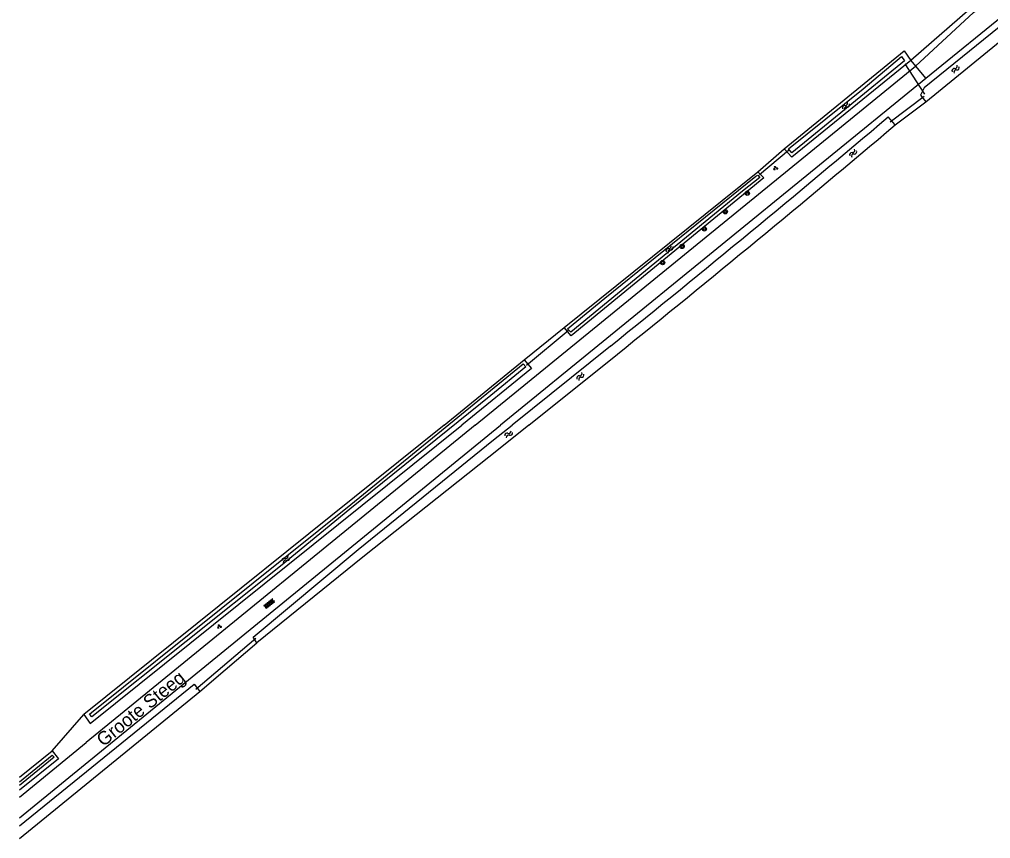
# Model space of a CAD drawing. Extents: x 136000 to 141014, y 402000 to 403500.
# Drawn here: x 136000 to 136180.8, y 402923.1 to 403075.5 of the extents above; entities that cross this region are included whole.
import ezdxf

# ---------------------------------------------------------------- set-up
doc = ezdxf.new("R2010")
doc.units = 0
for name, color, linetype in [('gg-anno-openbare ruimte label', 7, 'Continuous'), ('gg-knt-bronhoudergrens', 7, 'Continuous'), ('gg-knt-onverhard', 7, 'Continuous'), ('gg-kntw-bovenkant insteek waterloop', 7, 'Continuous'), ('gg-kntw-waterlijn', 7, 'Continuous'), ('gg-kwrk-duiker nz buis', 7, 'Continuous'), ('gt-grn-groengrens', 7, 'Continuous'), ('gt-grn-weggrens', 7, 'Continuous'), ('gt-symb-boom', 7, 'Continuous'), ('gt-symb-groenvak', 7, 'Continuous'), ('gt-symb-overige verharding', 7, 'Continuous'), ('gt-symb-watersymbool', 7, 'Continuous')]:
    doc.layers.add(name, color=color, linetype=linetype)

# ---------------------------------------------------------------- blocks, each defined once
blk = doc.blocks.new('gt0-BOOM')
at = {"layer": 'gt-symb-boom'}
for radius in [0.4, 0.2]:
    blk.add_circle((0, 0), radius, dxfattribs=at)
blk = doc.blocks.new('gt0-GRVAK')
at = {"layer": 'gt-symb-groenvak'}
for p, q in [((-0.11, 0.19), (-0.23, 0.24)), ((-0.18, 0.15), (0.09, 0.15)), ((-0.09, 0.21), (-0.16, 0.32)), ((-0.05, 0.21), (-0.05, 0.39)), ((0, 0.21), (0.06, 0.32)), ((0.02, 0.19), (0.13, 0.24)), ((0.26, -0.05), (0.2, 0.06)), ((0.31, -0.05), (0.31, 0.13)), ((0.35, -0.05), (0.41, 0.06)), ((-0.24, -0.23), (-0.36, -0.18)), ((-0.32, -0.26), (-0.05, -0.26)), ((-0.23, -0.21), (-0.29, -0.1)), ((-0.18, -0.2), (-0.18, -0.02)), ((-0.14, -0.21), (-0.07, -0.1)), ((-0.12, -0.23), (0, -0.18)), ((0.24, -0.07), (0.12, -0.02)), ((0.17, -0.11), (0.44, -0.11)), ((0.37, -0.07), (0.49, -0.02))]:
    blk.add_line(p, q, dxfattribs=at)
blk = doc.blocks.new('gt0-WA')
at = {"layer": 'gt-symb-watersymbool'}
for centre, start, end in [((-0.32, 0.02), 28.0725, 151.9275), ((0.43, 0.42), 208.0725, 331.9275), ((-0.32, -0.43), 28.0725, 151.9275), ((0.43, -0.03), 208.0725, 331.9275)]:
    blk.add_arc(centre, 0.425, start, end, dxfattribs=at)
blk = doc.blocks.new('gt0-OVH')
at = {"layer": 'gt-symb-overige verharding'}
for points in [[(-0.97, 0.3), (-0.97, 0.31), (-0.96, 0.32), (-0.97, 0.33), (-0.97, 0.34), (-0.98, 0.35), (-0.99, 0.35), (-1, 0.36), (-1.01, 0.35), (-1.02, 0.35), (-1.03, 0.34), (-1.03, 0.33), (-1.04, 0.32), (-1.03, 0.31), (-1.03, 0.3), (-1.02, 0.29), (-1.01, 0.29), (-1, 0.28), (-0.99, 0.29), (-0.98, 0.29)], [(-0.87, 0.11), (-0.87, 0.12), (-0.86, 0.13), (-0.87, 0.14), (-0.87, 0.15), (-0.88, 0.16), (-0.89, 0.16), (-0.9, 0.16), (-0.91, 0.16), (-0.92, 0.16), (-0.93, 0.15), (-0.93, 0.14), (-0.94, 0.13), (-0.93, 0.12), (-0.93, 0.11), (-0.92, 0.1), (-0.91, 0.09), (-0.9, 0.09), (-0.89, 0.09), (-0.88, 0.1)], [(-0.77, 0.3), (-0.77, 0.31), (-0.76, 0.32), (-0.77, 0.33), (-0.77, 0.34), (-0.78, 0.35), (-0.79, 0.35), (-0.8, 0.36), (-0.81, 0.35), (-0.82, 0.35), (-0.83, 0.34), (-0.83, 0.33), (-0.84, 0.32), (-0.83, 0.31), (-0.83, 0.3), (-0.82, 0.29), (-0.81, 0.29), (-0.8, 0.28), (-0.79, 0.29), (-0.78, 0.29)], [(-0.67, 0.11), (-0.67, 0.12), (-0.66, 0.13), (-0.67, 0.14), (-0.67, 0.15), (-0.68, 0.16), (-0.69, 0.16), (-0.7, 0.16), (-0.71, 0.16), (-0.72, 0.16), (-0.73, 0.15), (-0.73, 0.14), (-0.74, 0.13), (-0.73, 0.12), (-0.73, 0.11), (-0.72, 0.1), (-0.71, 0.09), (-0.7, 0.09), (-0.69, 0.09), (-0.68, 0.1)], [(-0.57, 0.3), (-0.57, 0.31), (-0.56, 0.32), (-0.57, 0.33), (-0.57, 0.34), (-0.58, 0.35), (-0.59, 0.35), (-0.6, 0.36), (-0.61, 0.35), (-0.62, 0.35), (-0.63, 0.34), (-0.63, 0.33), (-0.64, 0.32), (-0.63, 0.31), (-0.63, 0.3), (-0.62, 0.29), (-0.61, 0.29), (-0.6, 0.28), (-0.59, 0.29), (-0.58, 0.29)], [(-0.47, 0.11), (-0.47, 0.12), (-0.46, 0.13), (-0.47, 0.14), (-0.47, 0.15), (-0.48, 0.16), (-0.49, 0.16), (-0.5, 0.16), (-0.51, 0.16), (-0.52, 0.16), (-0.53, 0.15), (-0.53, 0.14), (-0.54, 0.13), (-0.53, 0.12), (-0.53, 0.11), (-0.52, 0.1), (-0.51, 0.09), (-0.5, 0.09), (-0.49, 0.09), (-0.48, 0.1)], [(-0.37, 0.3), (-0.37, 0.31), (-0.36, 0.32), (-0.37, 0.33), (-0.37, 0.34), (-0.38, 0.35), (-0.39, 0.35), (-0.4, 0.36), (-0.41, 0.35), (-0.42, 0.35), (-0.43, 0.34), (-0.43, 0.33), (-0.44, 0.32), (-0.43, 0.31), (-0.43, 0.3), (-0.42, 0.29), (-0.41, 0.29), (-0.4, 0.28), (-0.39, 0.29), (-0.38, 0.29)], [(-0.27, 0.11), (-0.27, 0.12), (-0.26, 0.13), (-0.27, 0.14), (-0.27, 0.15), (-0.28, 0.16), (-0.29, 0.16), (-0.3, 0.16), (-0.31, 0.16), (-0.32, 0.16), (-0.33, 0.15), (-0.33, 0.14), (-0.34, 0.13), (-0.33, 0.12), (-0.33, 0.11), (-0.32, 0.1), (-0.31, 0.09), (-0.3, 0.09), (-0.29, 0.09), (-0.28, 0.1)], [(-0.17, 0.3), (-0.17, 0.31), (-0.16, 0.32), (-0.17, 0.33), (-0.17, 0.34), (-0.18, 0.35), (-0.19, 0.35), (-0.2, 0.36), (-0.21, 0.35), (-0.22, 0.35), (-0.23, 0.34), (-0.23, 0.33), (-0.24, 0.32), (-0.23, 0.31), (-0.23, 0.3), (-0.22, 0.29), (-0.21, 0.29), (-0.2, 0.28), (-0.19, 0.29), (-0.18, 0.29)], [(-0.07, 0.11), (-0.07, 0.12), (-0.06, 0.13), (-0.07, 0.14), (-0.07, 0.15), (-0.08, 0.16), (-0.09, 0.16), (-0.1, 0.16), (-0.11, 0.16), (-0.12, 0.16), (-0.13, 0.15), (-0.13, 0.14), (-0.14, 0.13), (-0.13, 0.12), (-0.13, 0.11), (-0.12, 0.1), (-0.11, 0.09), (-0.1, 0.09), (-0.09, 0.09), (-0.08, 0.1)], [(0.03, 0.3), (0.03, 0.31), (0.04, 0.32), (0.03, 0.33), (0.03, 0.34), (0.02, 0.35), (0.01, 0.35), (0, 0.36), (-0.01, 0.35), (-0.02, 0.35), (-0.03, 0.34), (-0.03, 0.33), (-0.04, 0.32), (-0.03, 0.31), (-0.03, 0.3), (-0.02, 0.29), (-0.01, 0.29), (0, 0.28), (0.01, 0.29), (0.02, 0.29)], [(0.13, 0.11), (0.13, 0.12), (0.14, 0.13), (0.13, 0.14), (0.13, 0.15), (0.12, 0.16), (0.11, 0.16), (0.1, 0.16), (0.09, 0.16), (0.08, 0.16), (0.07, 0.15), (0.07, 0.14), (0.06, 0.13), (0.07, 0.12), (0.07, 0.11), (0.08, 0.1), (0.09, 0.09), (0.1, 0.09), (0.11, 0.09), (0.12, 0.1)], [(0.23, 0.3), (0.23, 0.31), (0.24, 0.32), (0.23, 0.33), (0.23, 0.34), (0.22, 0.35), (0.21, 0.35), (0.2, 0.36), (0.19, 0.35), (0.18, 0.35), (0.17, 0.34), (0.17, 0.33), (0.16, 0.32), (0.17, 0.31), (0.17, 0.3), (0.18, 0.29), (0.19, 0.29), (0.2, 0.28), (0.21, 0.29), (0.22, 0.29)], [(0.33, 0.11), (0.33, 0.12), (0.34, 0.13), (0.33, 0.14), (0.33, 0.15), (0.32, 0.16), (0.31, 0.16), (0.3, 0.16), (0.29, 0.16), (0.28, 0.16), (0.27, 0.15), (0.27, 0.14), (0.26, 0.13), (0.27, 0.12), (0.27, 0.11), (0.28, 0.1), (0.29, 0.09), (0.3, 0.09), (0.31, 0.09), (0.32, 0.1)], [(0.43, 0.3), (0.43, 0.31), (0.44, 0.32), (0.43, 0.33), (0.43, 0.34), (0.42, 0.35), (0.41, 0.35), (0.4, 0.36), (0.39, 0.35), (0.38, 0.35), (0.37, 0.34), (0.37, 0.33), (0.36, 0.32), (0.37, 0.31), (0.37, 0.3), (0.38, 0.29), (0.39, 0.29), (0.4, 0.28), (0.41, 0.29), (0.42, 0.29)], [(0.53, 0.11), (0.53, 0.12), (0.54, 0.13), (0.53, 0.14), (0.53, 0.15), (0.52, 0.16), (0.51, 0.16), (0.5, 0.16), (0.49, 0.16), (0.48, 0.16), (0.47, 0.15), (0.47, 0.14), (0.46, 0.13), (0.47, 0.12), (0.47, 0.11), (0.48, 0.1), (0.49, 0.09), (0.5, 0.09), (0.51, 0.09), (0.52, 0.1)], [(0.63, 0.3), (0.63, 0.31), (0.64, 0.32), (0.63, 0.33), (0.63, 0.34), (0.62, 0.35), (0.61, 0.35), (0.6, 0.36), (0.59, 0.35), (0.58, 0.35), (0.57, 0.34), (0.57, 0.33), (0.56, 0.32), (0.57, 0.31), (0.57, 0.3), (0.58, 0.29), (0.59, 0.29), (0.6, 0.28), (0.61, 0.29), (0.62, 0.29)], [(0.73, 0.11), (0.73, 0.12), (0.74, 0.13), (0.73, 0.14), (0.73, 0.15), (0.72, 0.16), (0.71, 0.16), (0.7, 0.16), (0.69, 0.16), (0.68, 0.16), (0.67, 0.15), (0.67, 0.14), (0.66, 0.13), (0.67, 0.12), (0.67, 0.11), (0.68, 0.1), (0.69, 0.09), (0.7, 0.09), (0.71, 0.09), (0.72, 0.1)], [(0.83, 0.3), (0.83, 0.31), (0.84, 0.32), (0.83, 0.33), (0.83, 0.34), (0.82, 0.35), (0.81, 0.35), (0.8, 0.36), (0.79, 0.35), (0.78, 0.35), (0.77, 0.34), (0.77, 0.33), (0.76, 0.32), (0.77, 0.31), (0.77, 0.3), (0.78, 0.29), (0.79, 0.29), (0.8, 0.28), (0.81, 0.29), (0.82, 0.29)], [(0.93, 0.11), (0.93, 0.12), (0.94, 0.13), (0.93, 0.14), (0.93, 0.15), (0.92, 0.16), (0.91, 0.16), (0.9, 0.16), (0.89, 0.16), (0.88, 0.16), (0.87, 0.15), (0.87, 0.14), (0.86, 0.13), (0.87, 0.12), (0.87, 0.11), (0.88, 0.1), (0.89, 0.09), (0.9, 0.09), (0.91, 0.09), (0.92, 0.1)], [(1.03, 0.3), (1.03, 0.31), (1.04, 0.32), (1.03, 0.33), (1.03, 0.34), (1.02, 0.35), (1.01, 0.35), (1, 0.36), (0.99, 0.35), (0.98, 0.35), (0.97, 0.34), (0.97, 0.33), (0.96, 0.32), (0.97, 0.31), (0.97, 0.3), (0.98, 0.29), (0.99, 0.29), (1, 0.28), (1.01, 0.29), (1.02, 0.29)], [(-0.97, -0.14), (-0.97, -0.13), (-0.96, -0.12), (-0.97, -0.11), (-0.97, -0.1), (-0.98, -0.09), (-0.99, -0.09), (-1, -0.08), (-1.01, -0.09), (-1.02, -0.09), (-1.03, -0.1), (-1.03, -0.11), (-1.04, -0.12), (-1.03, -0.13), (-1.03, -0.14), (-1.02, -0.15), (-1.01, -0.15), (-1, -0.16), (-0.99, -0.15), (-0.98, -0.15)], [(-0.87, -0.33), (-0.87, -0.32), (-0.86, -0.31), (-0.87, -0.3), (-0.87, -0.29), (-0.88, -0.28), (-0.89, -0.28), (-0.9, -0.28), (-0.91, -0.28), (-0.92, -0.28), (-0.93, -0.29), (-0.93, -0.3), (-0.94, -0.31), (-0.93, -0.32), (-0.93, -0.33), (-0.92, -0.34), (-0.91, -0.35), (-0.9, -0.35), (-0.89, -0.35), (-0.88, -0.34)], [(-0.77, -0.14), (-0.77, -0.13), (-0.76, -0.12), (-0.77, -0.11), (-0.77, -0.1), (-0.78, -0.09), (-0.79, -0.09), (-0.8, -0.08), (-0.81, -0.09), (-0.82, -0.09), (-0.83, -0.1), (-0.83, -0.11), (-0.84, -0.12), (-0.83, -0.13), (-0.83, -0.14), (-0.82, -0.15), (-0.81, -0.15), (-0.8, -0.16), (-0.79, -0.15), (-0.78, -0.15)], [(-0.67, -0.33), (-0.67, -0.32), (-0.66, -0.31), (-0.67, -0.3), (-0.67, -0.29), (-0.68, -0.28), (-0.69, -0.28), (-0.7, -0.28), (-0.71, -0.28), (-0.72, -0.28), (-0.73, -0.29), (-0.73, -0.3), (-0.74, -0.31), (-0.73, -0.32), (-0.73, -0.33), (-0.72, -0.34), (-0.71, -0.35), (-0.7, -0.35), (-0.69, -0.35), (-0.68, -0.34)], [(-0.57, -0.14), (-0.57, -0.13), (-0.56, -0.12), (-0.57, -0.11), (-0.57, -0.1), (-0.58, -0.09), (-0.59, -0.09), (-0.6, -0.08), (-0.61, -0.09), (-0.62, -0.09), (-0.63, -0.1), (-0.63, -0.11), (-0.64, -0.12), (-0.63, -0.13), (-0.63, -0.14), (-0.62, -0.15), (-0.61, -0.15), (-0.6, -0.16), (-0.59, -0.15), (-0.58, -0.15)], [(-0.47, -0.33), (-0.47, -0.32), (-0.46, -0.31), (-0.47, -0.3), (-0.47, -0.29), (-0.48, -0.28), (-0.49, -0.28), (-0.5, -0.28), (-0.51, -0.28), (-0.52, -0.28), (-0.53, -0.29), (-0.53, -0.3), (-0.54, -0.31), (-0.53, -0.32), (-0.53, -0.33), (-0.52, -0.34), (-0.51, -0.35), (-0.5, -0.35), (-0.49, -0.35), (-0.48, -0.34)], [(-0.37, -0.14), (-0.37, -0.13), (-0.36, -0.12), (-0.37, -0.11), (-0.37, -0.1), (-0.38, -0.09), (-0.39, -0.09), (-0.4, -0.08), (-0.41, -0.09), (-0.42, -0.09), (-0.43, -0.1), (-0.43, -0.11), (-0.44, -0.12), (-0.43, -0.13), (-0.43, -0.14), (-0.42, -0.15), (-0.41, -0.15), (-0.4, -0.16), (-0.39, -0.15), (-0.38, -0.15)], [(-0.27, -0.33), (-0.27, -0.32), (-0.26, -0.31), (-0.27, -0.3), (-0.27, -0.29), (-0.28, -0.28), (-0.29, -0.28), (-0.3, -0.28), (-0.31, -0.28), (-0.32, -0.28), (-0.33, -0.29), (-0.33, -0.3), (-0.34, -0.31), (-0.33, -0.32), (-0.33, -0.33), (-0.32, -0.34), (-0.31, -0.35), (-0.3, -0.35), (-0.29, -0.35), (-0.28, -0.34)], [(-0.17, -0.14), (-0.17, -0.13), (-0.16, -0.12), (-0.17, -0.11), (-0.17, -0.1), (-0.18, -0.09), (-0.19, -0.09), (-0.2, -0.08), (-0.21, -0.09), (-0.22, -0.09), (-0.23, -0.1), (-0.23, -0.11), (-0.24, -0.12), (-0.23, -0.13), (-0.23, -0.14), (-0.22, -0.15), (-0.21, -0.15), (-0.2, -0.16), (-0.19, -0.15), (-0.18, -0.15)], [(-0.07, -0.33), (-0.07, -0.32), (-0.06, -0.31), (-0.07, -0.3), (-0.07, -0.29), (-0.08, -0.28), (-0.09, -0.28), (-0.1, -0.28), (-0.11, -0.28), (-0.12, -0.28), (-0.13, -0.29), (-0.13, -0.3), (-0.14, -0.31), (-0.13, -0.32), (-0.13, -0.33), (-0.12, -0.34), (-0.11, -0.35), (-0.1, -0.35), (-0.09, -0.35), (-0.08, -0.34)], [(0.03, -0.14), (0.03, -0.13), (0.04, -0.12), (0.03, -0.11), (0.03, -0.1), (0.02, -0.09), (0.01, -0.09), (0, -0.08), (-0.01, -0.09), (-0.02, -0.09), (-0.03, -0.1), (-0.03, -0.11), (-0.04, -0.12), (-0.03, -0.13), (-0.03, -0.14), (-0.02, -0.15), (-0.01, -0.15), (0, -0.16), (0.01, -0.15), (0.02, -0.15)], [(0.13, -0.33), (0.13, -0.32), (0.14, -0.31), (0.13, -0.3), (0.13, -0.29), (0.12, -0.28), (0.11, -0.28), (0.1, -0.28), (0.09, -0.28), (0.08, -0.28), (0.07, -0.29), (0.07, -0.3), (0.06, -0.31), (0.07, -0.32), (0.07, -0.33), (0.08, -0.34), (0.09, -0.35), (0.1, -0.35), (0.11, -0.35), (0.12, -0.34)], [(0.23, -0.14), (0.23, -0.13), (0.24, -0.12), (0.23, -0.11), (0.23, -0.1), (0.22, -0.09), (0.21, -0.09), (0.2, -0.08), (0.19, -0.09), (0.18, -0.09), (0.17, -0.1), (0.17, -0.11), (0.16, -0.12), (0.17, -0.13), (0.17, -0.14), (0.18, -0.15), (0.19, -0.15), (0.2, -0.16), (0.21, -0.15), (0.22, -0.15)], [(0.33, -0.33), (0.33, -0.32), (0.34, -0.31), (0.33, -0.3), (0.33, -0.29), (0.32, -0.28), (0.31, -0.28), (0.3, -0.28), (0.29, -0.28), (0.28, -0.28), (0.27, -0.29), (0.27, -0.3), (0.26, -0.31), (0.27, -0.32), (0.27, -0.33), (0.28, -0.34), (0.29, -0.35), (0.3, -0.35), (0.31, -0.35), (0.32, -0.34)], [(0.43, -0.14), (0.43, -0.13), (0.44, -0.12), (0.43, -0.11), (0.43, -0.1), (0.42, -0.09), (0.41, -0.09), (0.4, -0.08), (0.39, -0.09), (0.38, -0.09), (0.37, -0.1), (0.37, -0.11), (0.36, -0.12), (0.37, -0.13), (0.37, -0.14), (0.38, -0.15), (0.39, -0.15), (0.4, -0.16), (0.41, -0.15), (0.42, -0.15)], [(0.53, -0.33), (0.53, -0.32), (0.54, -0.31), (0.53, -0.3), (0.53, -0.29), (0.52, -0.28), (0.51, -0.28), (0.5, -0.28), (0.49, -0.28), (0.48, -0.28), (0.47, -0.29), (0.47, -0.3), (0.46, -0.31), (0.47, -0.32), (0.47, -0.33), (0.48, -0.34), (0.49, -0.35), (0.5, -0.35), (0.51, -0.35), (0.52, -0.34)], [(0.63, -0.14), (0.63, -0.13), (0.64, -0.12), (0.63, -0.11), (0.63, -0.1), (0.62, -0.09), (0.61, -0.09), (0.6, -0.08), (0.59, -0.09), (0.58, -0.09), (0.57, -0.1), (0.57, -0.11), (0.56, -0.12), (0.57, -0.13), (0.57, -0.14), (0.58, -0.15), (0.59, -0.15), (0.6, -0.16), (0.61, -0.15), (0.62, -0.15)], [(0.73, -0.33), (0.73, -0.32), (0.74, -0.31), (0.73, -0.3), (0.73, -0.29), (0.72, -0.28), (0.71, -0.28), (0.7, -0.28), (0.69, -0.28), (0.68, -0.28), (0.67, -0.29), (0.67, -0.3), (0.66, -0.31), (0.67, -0.32), (0.67, -0.33), (0.68, -0.34), (0.69, -0.35), (0.7, -0.35), (0.71, -0.35), (0.72, -0.34)], [(0.83, -0.14), (0.83, -0.13), (0.84, -0.12), (0.83, -0.11), (0.83, -0.1), (0.82, -0.09), (0.81, -0.09), (0.8, -0.08), (0.79, -0.09), (0.78, -0.09), (0.77, -0.1), (0.77, -0.11), (0.76, -0.12), (0.77, -0.13), (0.77, -0.14), (0.78, -0.15), (0.79, -0.15), (0.8, -0.16), (0.81, -0.15), (0.82, -0.15)], [(0.93, -0.33), (0.93, -0.32), (0.94, -0.31), (0.93, -0.3), (0.93, -0.29), (0.92, -0.28), (0.91, -0.28), (0.9, -0.28), (0.89, -0.28), (0.88, -0.28), (0.87, -0.29), (0.87, -0.3), (0.86, -0.31), (0.87, -0.32), (0.87, -0.33), (0.88, -0.34), (0.89, -0.35), (0.9, -0.35), (0.91, -0.35), (0.92, -0.34)], [(1.03, -0.14), (1.03, -0.13), (1.04, -0.12), (1.03, -0.11), (1.03, -0.1), (1.02, -0.09), (1.01, -0.09), (1, -0.08), (0.99, -0.09), (0.98, -0.09), (0.97, -0.1), (0.97, -0.11), (0.96, -0.12), (0.97, -0.13), (0.97, -0.14), (0.98, -0.15), (0.99, -0.15), (1, -0.16), (1.01, -0.15), (1.02, -0.15)]]:
    blk.add_lwpolyline(points, close=True, dxfattribs=at)

msp = doc.modelspace()

# ---------------------------------------------------------------- linework, layer by layer
at = {"layer": 'gg-knt-bronhoudergrens'}
for p, q in [((136163.03, 403055.85), (136168.69, 403060.13)), ((136137.43, 403047.13), (136142.37, 403051.4)), ((136093.93, 403012.15), (136101.39, 403018.16)), ((136038.3, 402954.44), (136044.19, 402959.45)), ((136006.11, 402939.38), (136011.99, 402946.15))]:
    msp.add_line(p, q, dxfattribs=at)
msp.add_lwpolyline([(136451.02, 403300.26), (136417.69, 403273.18), (136374.33, 403237.86), (136321.97, 403195.49), (136273.92, 403155.39), (136227, 403118.07), (136197.85, 403094.49), (136176.99, 403077.43), (136165.93, 403067.82)], dxfattribs=at)
at = {"layer": 'gg-knt-onverhard'}
for p, q in [((136354.88, 403216.05), (136168.69, 403064.44)), ((136084.86, 403000), (136166.78, 403066.78)), ((136168.69, 403064.44), (136089.55, 403000)), ((136009.18, 402934.42), (136089.55, 403000)), ((136084.86, 403000), (136012.44, 402940.91)), ((136000, 402930.76), (136012.44, 402940.91)), ((136000, 402926.93), (136009.18, 402934.42))]:
    msp.add_line(p, q, dxfattribs=at)
msp.add_lwpolyline([(136166.78, 403066.78), (136177.57, 403076.76), (136198.41, 403093.82), (136227.55, 403117.39), (136274.48, 403154.71), (136322.52, 403194.81), (136374.89, 403237.18), (136418.24, 403272.5), (136447.05, 403295.84)], dxfattribs=at)
at = {"layer": 'gg-kntw-bovenkant insteek waterloop'}
for p, q in [((136168.69, 403060.13), (136265.83, 403139.28)), ((136163.03, 403055.85), (136161.73, 403057.33)), ((136101.39, 403018.16), (136137.43, 403047.13)), ((136110.01, 403014.68), (136091.69, 403000)), ((136079.08, 403000), (136093.93, 403012.15)), ((136094.84, 403000), (136111.31, 403013.2)), ((136079.08, 403000), (136011.99, 402946.15)), ((136088.27, 402997.26), (136091.69, 403000)), ((136094.84, 403000), (136089.5, 402995.72)), ((136000, 402923.07), (136033.6, 402950.43)), ((136000, 402934.47), (136006.11, 402939.38))]:
    msp.add_line(p, q, dxfattribs=at)
for points in [[(136265.83, 403139.28), (136264.81, 403140.72), (136168.42, 403062.75), (136167.72, 403061.4), (136168.69, 403060.13)], [(136142.37, 403051.4), (136164.69, 403069.64), (136165.93, 403067.82)], [(136165.93, 403067.82), (136143.77, 403049.83), (136142.37, 403051.4)], [(136137.43, 403047.13), (136138.54, 403045.99), (136102.73, 403016.57), (136101.39, 403018.16)], [(136093.93, 403012.15), (136095.32, 403010.51), (136082.35, 403000)], [(136011.99, 402946.15), (136013.15, 402944.45), (136082.35, 403000)], [(136044.19, 402959.45), (136043.53, 402960.53), (136063.07, 402976.86), (136088.27, 402997.26)], [(136089.5, 402995.72), (136063.95, 402975.44), (136044.19, 402959.45)], [(136000, 402925.42), (136032.53, 402951.79), (136033.6, 402950.43)], [(136006.11, 402939.38), (136007.27, 402937.93), (136000, 402932.07)]]:
    msp.add_lwpolyline(points, dxfattribs=at)
for centre in [(134352.35, 405198.88), (134353.65, 405197.39)]:
    msp.add_arc(centre, 2803.58, 308.82437, 310.19422, dxfattribs=at)
at = {"layer": 'gg-kntw-waterlijn'}
for points in [[(136143.16, 403051.37), (136157.08, 403062.57), (136164.22, 403068.57), (136164.73, 403067.77), (136143.75, 403050.67), (136143.16, 403051.37)], [(136102.01, 403017.92), (136108.97, 403023.61), (136137.1, 403046.31), (136137.46, 403046.47), (136137.85, 403046.06), (136134.6, 403043.49), (136102.65, 403017.29), (136102.01, 403017.92)], [(136013.42, 402946.49), (136061.69, 402985.19), (136093.78, 403011.41), (136094.27, 403010.82), (136087.74, 403005.48), (136061.51, 402984.35), (136048.58, 402973.75), (136013.49, 402945.7), (136013.06, 402946.23), (136013.42, 402946.49)], [(136000, 402933.64), (136006.1, 402938.6), (136006.45, 402938.18), (136000, 402932.94)]]:
    msp.add_lwpolyline(points, dxfattribs=at)
at = {"layer": 'gg-kwrk-duiker nz buis'}
for p, q in [((136168.53, 403061.54), (136164.89, 403067.23)), ((136168.44, 403061.11), (136162.08, 403056.36)), ((136143.13, 403051.1), (136137.77, 403046.53)), ((136102.15, 403017.51), (136094.39, 403011.07)), ((136032.86, 402950.88), (136044.01, 402960.33))]:
    msp.add_line(p, q, dxfattribs=at)
at = {"layer": 'gt-grn-groengrens'}
for p, q in [((136165.93, 403067.82), (136166.78, 403066.78)), ((136033.6, 402950.43), (136038.3, 402954.44))]:
    msp.add_line(p, q, dxfattribs=at)
at = {"layer": 'gt-grn-weggrens'}
msp.add_line((136166.78, 403066.78), (136168.69, 403064.44), dxfattribs=at)

# ---------------------------------------------------------------- block references
at = {"layer": 'gt-symb-boom'}
for p in [(136135.49, 403043.13), (136131.38, 403039.68), (136127.49, 403036.48), (136123.36, 403033.24), (136119.73, 403030.22)]:
    msp.add_blockref('gt0-BOOM', p, dxfattribs=at)
at = {"layer": 'gt-symb-groenvak'}
for p in [(136140.73, 403047.8), (136037.2, 402962.52)]:
    msp.add_blockref('gt0-GRVAK', p, dxfattribs=at)
at = {"layer": 'gt-symb-overige verharding', "rotation": 38.95496029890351}
msp.add_blockref('gt0-OVH', (136046.52, 402966.76), dxfattribs=at)
at = {"layer": 'gt-symb-watersymbool'}
for p, rotation in [((136174.29, 403066.24), -126.99589775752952), ((136153.89, 403059.35), -126.99589775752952), ((136155.23, 403050.6), -126.99589775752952), ((136121.04, 403032.74), -126.99589775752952), ((136104.45, 403009.06), -126.99589775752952), ((136091.02, 402998.26), 38.990994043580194), ((136049.51, 402974.97), 38.82982490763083)]:
    msp.add_blockref('gt0-WA', p, dxfattribs=dict(at, rotation=rotation))

# ---------------------------------------------------------------- texts
at = {"layer": 'gg-anno-openbare ruimte label'}
msp.add_text('Groote Steeg', height=2.5, rotation=38.9, dxfattribs=at).set_placement((136015.62, 402940.05))

doc.saveas('drawing.dxf')
